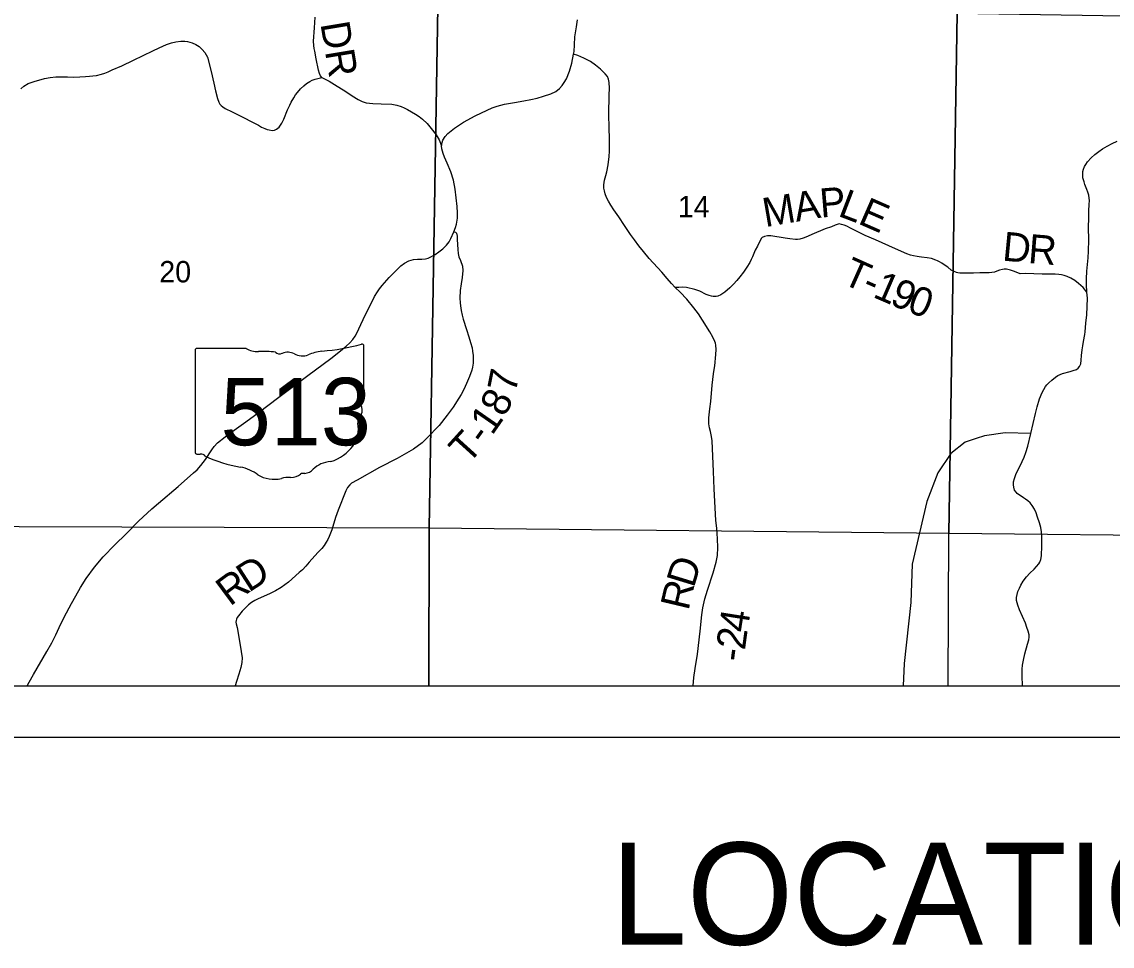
# Model space of a CAD drawing. Extents: x 0 to 34, y 0 to 22.
# Drawn here: x 3.275 to 5.408, y 13.591 to 15.399 of the extents above; entities that cross this region are included whole.
import ezdxf

# ---------------------------------------------------------------- set-up
doc = ezdxf.new("R2010")
doc.units = 0
for name, color, linetype in [('GM_X_Corporation', 7, 'Continuous'), ('GM_X_County_Road', 7, 'Continuous'), ('GM_X_County_Road_Text', 7, 'Continuous'), ('GM_X_Section_Text', 7, 'Continuous'), ('GM_X_State_Location', 7, 'Continuous'), ('GM_X_State_Route', 7, 'Continuous'), ('GM_X_State_Shield', 7, 'Continuous'), ('GM_X_Township_Road', 7, 'Continuous'), ('GM_X_Township_Road_Text', 7, 'Continuous'), ('GM_X_Township_Text', 7, 'Continuous'), ('SH_Data', 7, 'Continuous'), ('SH_Text', 7, 'Continuous')]:
    doc.layers.add(name, color=color, linetype=linetype)

msp = doc.modelspace()

# ---------------------------------------------------------------- linework, layer by layer
at = {"layer": 'GM_X_Corporation'}
for points in [[(3.0813, 15.4398), (4.0887, 15.4288), (4.0718, 14.4088), (3.0687, 14.4122)], [(4.0887, 15.4288), (5.1041, 15.416), (5.088, 14.3982), (4.0718, 14.4088)], [(5.1041, 15.416), (6.1226, 15.3998), (6.117, 14.3875), (5.088, 14.3982)], [(3.065, 14.1), (4.0712, 14.1), (4.0718, 14.4088), (3.0687, 14.4122)], [(4.0712, 14.1), (5.0867, 14.1), (5.088, 14.3982), (4.0718, 14.4088)]]:
    msp.add_lwpolyline(points, close=True, dxfattribs=at)
at = {"layer": 'GM_X_County_Road'}
msp.add_lwpolyline([(4.5879, 14.1), (4.5895, 14.1163), (4.5918, 14.1341), (4.5964, 14.1619), (4.6017, 14.2072), (4.6049, 14.2392), (4.6069, 14.253), (4.6106, 14.2702), (4.6158, 14.2874), (4.6272, 14.321), (4.6329, 14.3423), (4.6353, 14.355), (4.6359, 14.3706), (4.6355, 14.3878), (4.6343, 14.4089), (4.6325, 14.4237), (4.6288, 14.4857), (4.628, 14.5193), (4.625, 14.5798), (4.6238, 14.5883), (4.6217, 14.5975), (4.6198, 14.6053), (4.6187, 14.6128), (4.6185, 14.6179), (4.6188, 14.6247), (4.6206, 14.6419), (4.6222, 14.6563), (4.6254, 14.6883), (4.628, 14.7106), (4.6286, 14.7153), (4.6303, 14.7265), (4.6325, 14.7485), (4.633, 14.7585), (4.6323, 14.7666), (4.6313, 14.7706), (4.6302, 14.7738), (4.6262, 14.7824), (4.6204, 14.7928), (4.6063, 14.8155), (4.5982, 14.8278), (4.5892, 14.8398), (4.5758, 14.857), (4.5625, 14.8707), (4.5529, 14.8797), (4.5455, 14.8873), (4.5368, 14.8969), (4.5265, 14.9092), (4.5021, 14.936), (4.4906, 14.9497), (4.4819, 14.961), (4.473, 14.9729), (4.4653, 14.9833), (4.4538, 15.0006), (4.4424, 15.0181), (4.433, 15.0317), (4.4268, 15.0404), (4.4223, 15.0481), (4.4183, 15.0557), (4.4155, 15.0628), (4.4144, 15.0685), (4.4134, 15.0739), (4.4131, 15.0806), (4.4147, 15.0898), (4.417, 15.0986), (4.4192, 15.1061), (4.4219, 15.1192), (4.4237, 15.1359), (4.4242, 15.1465), (4.4242, 15.1561), (4.424, 15.1709), (4.4236, 15.1911), (4.4229, 15.2184), (4.4238, 15.256), (4.4244, 15.2692), (4.4238, 15.2808), (4.4226, 15.2874), (4.4201, 15.2925), (4.416, 15.2975), (4.4065, 15.3066), (4.3972, 15.3144), (4.3872, 15.3216), (4.3742, 15.3284), (4.3625, 15.3336), (4.3541, 15.3362)], dxfattribs=at)
at = {"layer": 'GM_X_State_Route'}
msp.add_lwpolyline([(3.2854, 14.1), (3.2894, 14.1076), (3.2977, 14.1227), (3.3236, 14.1677), (3.3333, 14.1841), (3.3416, 14.2003), (3.3479, 14.2141), (3.358, 14.2347), (3.3719, 14.2615), (3.3805, 14.2765), (3.3896, 14.2924), (3.4009, 14.3099), (3.4173, 14.3327), (3.4342, 14.3524), (3.4568, 14.3758), (3.4787, 14.3976), (3.5039, 14.4233), (3.5199, 14.4379), (3.5291, 14.4462), (3.5422, 14.4577), (3.5807, 14.4901), (3.6109, 14.5168), (3.6176, 14.5231), (3.6251, 14.5312), (3.6339, 14.5428), (3.6464, 14.5622), (3.6513, 14.5687), (3.6576, 14.5759), (3.6726, 14.5872), (3.69, 14.6002), (3.713, 14.617), (3.7369, 14.6345), (3.7774, 14.6648), (3.834, 14.7071), (3.8792, 14.7406), (3.8984, 14.7555), (3.909, 14.7645), (3.9165, 14.7713), (3.9221, 14.778), (3.9266, 14.7844), (3.9298, 14.7899), (3.9343, 14.7985), (3.9467, 14.8252), (3.9561, 14.8446), (3.9649, 14.8616), (3.9706, 14.871), (3.9746, 14.8769), (3.9798, 14.8836), (3.9936, 14.8994), (4.0074, 14.9135), (4.0164, 14.9218), (4.0234, 14.9271), (4.0318, 14.9317), (4.0365, 14.9332), (4.0408, 14.934), (4.0489, 14.9347), (4.0575, 14.9347), (4.0641, 14.9356), (4.0693, 14.937), (4.0738, 14.9389), (4.0832, 14.9441), (4.0906, 14.9491), (4.0981, 14.9551), (4.1055, 14.9624), (4.1082, 14.9657), (4.1104, 14.969), (4.114, 14.9752), (4.1199, 14.9883), (4.1229, 14.9967), (4.1248, 15.0034), (4.127, 15.0154), (4.1271, 15.0257), (4.1263, 15.0383), (4.1244, 15.0552), (4.1225, 15.072), (4.1195, 15.0898), (4.1138, 15.1061), (4.1065, 15.1225), (4.1017, 15.1345), (4.0988, 15.1417), (4.0966, 15.1508), (4.096, 15.1567), (4.0969, 15.1629), (4.0985, 15.1677), (4.1026, 15.1747), (4.1081, 15.181), (4.121, 15.191), (4.1387, 15.2028), (4.1614, 15.2156), (4.1851, 15.2267), (4.1948, 15.2308), (4.2048, 15.234), (4.2187, 15.238), (4.2384, 15.2417), (4.2568, 15.2444), (4.2702, 15.2471), (4.283, 15.2498), (4.2954, 15.2537), (4.3097, 15.2582), (4.3193, 15.2632), (4.3266, 15.2687), (4.3318, 15.2744), (4.3359, 15.2805), (4.3399, 15.2878), (4.3461, 15.3028), (4.3508, 15.3182), (4.3541, 15.3362), (4.3549, 15.3411), (4.3556, 15.3545), (4.3565, 15.3698), (4.3597, 15.3897), (4.3618, 15.4031)], dxfattribs=at)
at = {"layer": 'GM_X_State_Shield'}
for p, q in [((3.7139, 14.7604), (3.6173, 14.7604)), ((3.9437, 14.6606), (3.9437, 14.7653)), ((3.6141, 14.7569), (3.6141, 14.5568)), ((3.9436, 14.6607), (3.9437, 14.6606))]:
    msp.add_line(p, q, dxfattribs=at)
for centre, major_axis, start_param, end_param in [((3.6179, 14.7573), (0.00382, 0), 1.712693, 3.28349), ((3.7368, 14.7836), (0.037, 0), 4.042523, 4.731795), ((3.8263, 15.0332), (0.3495, 0), 4.814394, 5.042369), ((3.94, 14.7657), (0.00367, 0), 6.141152, 7.989035), ((3.7491, 14.648), (0.133, 0), 1.404758, 1.657858), ((3.7793, 14.7584), (0.0107, 0), 3.836095, 5.185415), ((3.795, 14.7352), (0.0222, 0), 0.950623, 2.079405), ((3.8237, 14.767), (0.0267, 0), 4.081561, 5.145723), ((3.8708, 14.6992), (0.0703, 0), 1.699011, 2.107814), ((3.9428, 14.6529), (0.00568, 0), 1.883978, 3.671073), ((3.9398, 14.6602), (0.00393, 0), 5.05454, 6.418171), ((3.9568, 14.6168), (0.0248, 0), 2.387724, 3.262537), ((3.9067, 14.6397), (0.0341, 0), 5.934695, 6.695948), ((3.8458, 14.6035), (0.0874, 0), 5.101752, 6.440018), ((3.6179, 14.5564), (0.00385, 0), 3.00124, 4.508301), ((3.6185, 14.5768), (0.0294, 0), 4.665946, 4.897461), ((3.6245, 14.5452), (0.0106, 0), 0.519207, 1.627899), ((3.7583, 14.725), (0.2524, 0), 4.195997, 4.488961), ((3.6831, 14.4669), (0.079, 0), 0.823519, 1.323587), ((3.822, 14.5374), (0.0282, 0), 4.937069, 5.64225), ((3.8827, 14.5006), (0.0479, 0), 1.647645, 2.488434), ((3.7685, 14.5443), (0.0501, 0), 4.026481, 4.996735), ((3.7974, 14.4751), (0.0412, 0), 1.495662, 1.94098), ((3.8011, 14.5293), (0.0267, 0), 4.691044, 5.507374), ((3.8252, 14.5099), (0.00752, 0), 1.147584, 2.315152)]:
    msp.add_ellipse(centre, major_axis=major_axis, ratio=0.8, start_param=start_param, end_param=end_param, dxfattribs=at)
at = {"layer": 'GM_X_Township_Road'}
for points in [[(3.8619, 15.2903), (3.8591, 15.2939), (3.857, 15.2982), (3.8549, 15.3045), (3.8503, 15.3271), (3.8478, 15.3416), (3.8467, 15.3469), (3.8457, 15.3532), (3.8454, 15.3615), (3.846, 15.3701), (3.8467, 15.3793), (3.8475, 15.3878), (3.8488, 15.4087)], [(3.2732, 15.2682), (3.279, 15.2737), (3.2871, 15.2787), (3.2989, 15.2828), (3.3192, 15.2886), (3.3305, 15.2902), (3.3414, 15.2914), (3.3539, 15.2916), (3.3642, 15.2915), (3.375, 15.291), (3.3884, 15.2917), (3.3997, 15.2924), (3.4072, 15.2931), (3.4137, 15.2937), (3.4212, 15.2946), (3.4309, 15.2968), (3.4375, 15.2989), (3.4438, 15.3015), (3.4518, 15.3051), (3.4702, 15.3134), (3.4934, 15.3243), (3.5309, 15.3424), (3.5438, 15.3487), (3.5579, 15.3549), (3.5673, 15.3581), (3.576, 15.36), (3.5857, 15.3613), (3.594, 15.3612), (3.5992, 15.3606), (3.608, 15.3585), (3.615, 15.3552), (3.6218, 15.3507), (3.6276, 15.345), (3.6326, 15.3391), (3.6379, 15.33), (3.6449, 15.3022), (3.6504, 15.2794), (3.6538, 15.2645), (3.6576, 15.249), (3.6603, 15.2421), (3.6622, 15.2385), (3.6649, 15.2353), (3.6677, 15.233), (3.6726, 15.23), (3.6862, 15.2234), (3.7059, 15.2137), (3.7271, 15.2023), (3.7375, 15.1968), (3.7436, 15.1934), (3.7503, 15.1904), (3.7547, 15.1888), (3.7588, 15.1877), (3.7643, 15.1869), (3.7689, 15.1876), (3.7731, 15.189), (3.7781, 15.1929), (3.7833, 15.2012), (3.7871, 15.2089), (3.7945, 15.2268), (3.7989, 15.2363), (3.8016, 15.2424), (3.8066, 15.2508), (3.8101, 15.2563), (3.8138, 15.2609), (3.8198, 15.268), (3.8262, 15.2738), (3.8319, 15.2783), (3.8383, 15.2823), (3.8429, 15.2849), (3.8488, 15.2872), (3.8619, 15.2903)], [(3.8619, 15.2903), (3.8762, 15.2832), (3.8867, 15.2769), (3.9086, 15.2632), (3.9213, 15.2545), (3.9327, 15.2473), (3.9407, 15.2437), (3.9486, 15.241), (3.9611, 15.2394), (3.9775, 15.2388), (3.9983, 15.2379), (4.0083, 15.2361), (4.0165, 15.2336), (4.0229, 15.2312), (4.0292, 15.2276), (4.0368, 15.2234), (4.0451, 15.2185), (4.052, 15.2142), (4.0585, 15.2088), (4.0675, 15.2001), (4.0752, 15.1909), (4.0854, 15.1779), (4.0911, 15.1684), (4.096, 15.1567)], [(5.2319, 14.1), (5.2313, 14.12), (5.2313, 14.133), (5.2324, 14.1404), (5.2338, 14.1507), (5.2367, 14.1629), (5.2416, 14.1816), (5.2444, 14.1903), (5.2451, 14.1954), (5.2448, 14.2003), (5.2429, 14.2071), (5.2407, 14.2144), (5.2378, 14.2226), (5.2265, 14.2488), (5.223, 14.2582), (5.2216, 14.2623), (5.2203, 14.267), (5.2206, 14.2728), (5.2216, 14.2792), (5.2232, 14.2848), (5.2263, 14.2915), (5.2288, 14.297), (5.2335, 14.3048), (5.24, 14.3134), (5.2464, 14.3205), (5.255, 14.3285), (5.2639, 14.3388), (5.2662, 14.342), (5.2681, 14.3472), (5.2693, 14.3546), (5.2699, 14.3743), (5.27, 14.3926), (5.2695, 14.4016), (5.2678, 14.4102), (5.2651, 14.419), (5.2612, 14.4303), (5.2585, 14.4387), (5.2557, 14.4461), (5.2513, 14.4528), (5.2469, 14.4581), (5.2428, 14.4621), (5.2379, 14.4657), (5.2338, 14.4682), (5.2297, 14.471), (5.2245, 14.4743), (5.2216, 14.4765), (5.2197, 14.4791), (5.2165, 14.4832), (5.215, 14.4887), (5.2144, 14.4935), (5.2147, 14.4991), (5.2162, 14.5056), (5.2189, 14.5134), (5.2315, 14.5388), (5.2353, 14.5475), (5.2389, 14.5569), (5.2427, 14.5694), (5.2482, 14.5938), (5.2575, 14.6327), (5.2609, 14.6459), (5.2651, 14.6614), (5.2704, 14.6739), (5.2737, 14.6802), (5.277, 14.6856), (5.2796, 14.689), (5.2837, 14.6931), (5.2897, 14.6985), (5.2965, 14.7044), (5.3011, 14.7075), (5.3055, 14.7095), (5.3104, 14.7111), (5.3254, 14.7152), (5.331, 14.7171), (5.3375, 14.7193), (5.3412, 14.7218), (5.3438, 14.725), (5.346, 14.7304), (5.3471, 14.7372), (5.3476, 14.7462), (5.349, 14.7575), (5.35, 14.7656), (5.3514, 14.774), (5.3537, 14.7875), (5.3546, 14.7931), (5.356, 14.81), (5.3579, 14.8261), (5.3589, 14.8586), (5.3582, 14.8705), (5.3574, 14.8855), (5.3572, 14.8963), (5.3578, 14.9118), (5.3604, 14.9376), (5.3612, 14.9508), (5.3617, 14.973), (5.3611, 14.9971), (5.3615, 15.0161), (5.3618, 15.0296), (5.3624, 15.042), (5.3629, 15.0497), (5.3625, 15.0546), (5.3619, 15.0599), (5.3601, 15.066), (5.3581, 15.0713), (5.3542, 15.0811), (5.3525, 15.086), (5.3502, 15.094), (5.3498, 15.0985), (5.3499, 15.1032), (5.3503, 15.1067), (5.3512, 15.111), (5.3534, 15.1163), (5.3559, 15.1204), (5.3593, 15.1254), (5.3661, 15.133), (5.3735, 15.1396), (5.3815, 15.1459), (5.3885, 15.1507), (5.3978, 15.1562), (5.4075, 15.1611), (5.4173, 15.1656)], [(5.3582, 14.8705), (5.3507, 14.8793), (5.3419, 14.8873), (5.3344, 14.8931), (5.3266, 14.8979), (5.3194, 14.9012), (5.3133, 14.9033), (5.3081, 14.9043), (5.303, 14.905), (5.2961, 14.9055), (5.2835, 14.9054), (5.2705, 14.9056), (5.2381, 14.9068), (5.2277, 14.9065), (5.2167, 14.9105), (5.2089, 14.9135), (5.2009, 14.9151), (5.1965, 14.9153), (5.1927, 14.9149), (5.1871, 14.9136), (5.182, 14.9115), (5.1775, 14.9098), (5.1719, 14.9087), (5.1668, 14.9084), (5.1579, 14.9081), (5.1486, 14.9082), (5.1362, 14.9076), (5.1269, 14.9074), (5.1181, 14.9074), (5.1092, 14.9075), (5.1057, 14.908), (5.1029, 14.9087), (5.097, 14.9112), (5.0924, 14.9137), (5.0858, 14.9191), (5.0791, 14.924), (5.0742, 14.9271), (5.0695, 14.9297), (5.066, 14.9316), (5.0625, 14.9331), (5.054, 14.936), (5.0455, 14.9377), (5.0343, 14.9389), (5.0299, 14.9394), (5.0263, 14.9399), (5.0191, 14.9415), (5.0127, 14.9429), (5.0058, 14.9455), (4.9838, 14.9553), (4.9445, 14.9728), (4.9246, 14.9815), (4.8959, 14.9957), (4.8888, 14.9992), (4.8836, 15.0015), (4.878, 15.0031), (4.8735, 15.0038), (4.8693, 15.0027), (4.8655, 15.0012), (4.8582, 14.9985), (4.8463, 14.9941), (4.8416, 14.9921), (4.8245, 14.985), (4.8086, 14.9781), (4.8034, 14.9763), (4.7965, 14.9744), (4.7919, 14.9737), (4.788, 14.9736), (4.7773, 14.9747), (4.7678, 14.9758), (4.7399, 14.9805), (4.7331, 14.9805), (4.7274, 14.9795), (4.7231, 14.9776), (4.7208, 14.9757), (4.7135, 14.9604), (4.7092, 14.9523), (4.7063, 14.9463), (4.7037, 14.9398), (4.7012, 14.9344), (4.6985, 14.9286), (4.693, 14.9194), (4.6861, 14.9098), (4.6793, 14.9007), (4.6732, 14.893), (4.6668, 14.886), (4.6594, 14.8786), (4.6496, 14.8706), (4.6419, 14.8655), (4.6364, 14.8627), (4.6331, 14.862), (4.6304, 14.8616), (4.6268, 14.8618), (4.6235, 14.8624), (4.6195, 14.8636), (4.6136, 14.8661), (4.6008, 14.8721), (4.5913, 14.8755), (4.5748, 14.8792), (4.5666, 14.8803), (4.5597, 14.8794), (4.5529, 14.8797)], [(4.1199, 14.9883), (4.1228, 14.9875), (4.1251, 14.9856), (4.1262, 14.9797), (4.1266, 14.9734), (4.1275, 14.9537), (4.1286, 14.9459), (4.1298, 14.9397), (4.1328, 14.9321), (4.1365, 14.921), (4.1375, 14.9128), (4.1359, 14.8989), (4.1339, 14.8869), (4.1321, 14.8736), (4.1315, 14.8588), (4.1321, 14.8497), (4.1328, 14.8434), (4.1344, 14.8343), (4.1361, 14.8257), (4.1383, 14.8178), (4.1449, 14.7974), (4.1492, 14.7831), (4.1524, 14.7718), (4.1555, 14.7616), (4.1565, 14.755), (4.1578, 14.7463), (4.1579, 14.7382), (4.1577, 14.7312), (4.1564, 14.7236), (4.155, 14.7176), (4.1505, 14.7052), (4.1444, 14.6915), (4.1391, 14.6797), (4.1341, 14.6705), (4.1294, 14.6627), (4.1184, 14.6452), (4.1071, 14.6296), (4.0909, 14.6097), (4.0672, 14.5847), (4.058, 14.5757), (4.0408, 14.5634), (4.0272, 14.5552), (4.0089, 14.5448), (3.9744, 14.5272), (3.9305, 14.5024), (3.9199, 14.4965), (3.9164, 14.4937), (3.9117, 14.4884), (3.9084, 14.4815), (3.8933, 14.4438), (3.8908, 14.4367), (3.8886, 14.4297), (3.8809, 14.4055), (3.8759, 14.3927), (3.8734, 14.3864), (3.8702, 14.3813), (3.8659, 14.3746), (3.8619, 14.3692), (3.854, 14.361), (3.8369, 14.342), (3.8305, 14.3343), (3.8239, 14.3275), (3.8176, 14.322), (3.7966, 14.3032), (3.7894, 14.2977), (3.7822, 14.2927), (3.7712, 14.2864), (3.7592, 14.2801), (3.737, 14.2703), (3.7304, 14.267), (3.724, 14.2633), (3.7185, 14.2588), (3.7141, 14.2546), (3.706, 14.246), (3.6989, 14.2373), (3.6963, 14.2338), (3.6946, 14.2308), (3.6938, 14.2278), (3.6937, 14.2248), (3.694, 14.2215), (3.6958, 14.2144), (3.7017, 14.1798), (3.7056, 14.1549), (3.7054, 14.146), (3.7029, 14.1358), (3.699, 14.1231), (3.6945, 14.1087), (3.6921, 14.1)], [(5.2482, 14.5938), (5.1984, 14.5955), (5.1577, 14.5892), (5.1417, 14.5839)], [(5.1417, 14.5839), (5.1357, 14.5819), (5.1201, 14.5767), (5.0919, 14.5547), (5.0668, 14.5171), (5.0448, 14.4607), (5.0166, 14.3385), (5.0135, 14.2633), (5.0009, 14.1442), (4.9984, 14.1)]]:
    msp.add_lwpolyline(points, dxfattribs=at)
at = {"layer": 'GM_X_Township_Text'}
msp.add_lwpolyline([(2.6249, 19.1744), (2.6223, 19.0497), (2.622, 19.0358), (2.6202, 18.9481), (2.604, 17.9706), (2.6039, 17.9669), (2.5791, 16.4754), (2.4938, 16.4762), (2.1, 16.4804), (2.1, 14.1), (7.1227, 14.1)], dxfattribs=at)
at = {"layer": 'SH_Data'}
for p, q in [((2.1, 14.1), (8.9, 14.1)), ((2, 14), (9, 14))]:
    msp.add_line(p, q, dxfattribs=at)

# ---------------------------------------------------------------- texts
at = {"layer": 'GM_X_County_Road_Text'}
for s, rotation, p in [('D', 72.9222, (4.589, 14.2903)), ('R', 76.6321, (4.5785, 14.2459)), ('4', 81.0814, (4.6937, 14.2028)), ('2', 82.3382, (4.6891, 14.1688)), ('-', 82.3931, (4.6861, 14.1458))]:
    msp.add_text(s, height=0.0568, rotation=rotation, dxfattribs=at).set_placement(p)
at = {"layer": 'GM_X_Section_Text'}
for s, p in [('14', (4.5579, 15.0169)), ('20', (3.5437, 14.8895))]:
    msp.add_text(s, height=0.04186, rotation=0, dxfattribs=at).set_placement(p)
at = {"layer": 'GM_X_State_Location'}
for s in ['s', 'r']:
    msp.add_text(s, height=0.000189, dxfattribs=at).set_placement((3.7752, 14.6435))
msp.add_text('513', height=0.000189, rotation=0, dxfattribs=at).set_placement((3.7083, 14.6298))
at = {"layer": 'GM_X_State_Shield'}
msp.add_text('513', height=0.13184, dxfattribs=at).set_placement((3.6636, 14.5709))
at = {"layer": 'GM_X_Township_Road_Text'}
for s, height, rotation, p in [('DR', 0.05682, 279.4626, (3.8587, 15.3957)), ('M', 0.0568, 9.7678, (4.7288, 14.9975)), ('A', 0.0568, 9.7073, (4.7896, 15.0079)), ('P', 0.0568, 4.7522, (4.8376, 15.0162)), ('L', 0.0568, 339.0422, (4.8691, 15.0203)), ('E', 0.0568, 336.3878, (4.9082, 15.0054)), ('D', 0.0568, 354.575, (5.1913, 14.9324)), ('R', 0.0568, 355.4077, (5.2419, 14.9276)), ('T', 0.0568, 335.9657, (4.8765, 14.8886)), ('-', 0.0568, 336.1185, (4.9154, 14.8712)), ('1', 0.0568, 336.6202, (4.9373, 14.8616)), ('9', 0.0568, 337.4374, (4.9702, 14.8473)), ('0', 0.0568, 338.6826, (5.0038, 14.8334)), ('7', 0.0568, 78.6999, (4.2406, 14.6717)), ('8', 0.0568, 62.6028, (4.2187, 14.6242)), ('1', 0.0568, 55.2072, (4.1946, 14.5886)), ('T', 0.0568, 47.7799, (4.1475, 14.5319)), ('-', 0.0568, 54.3877, (4.1805, 14.5689)), ('D', 0.0568, 32.8302, (3.7186, 14.2819)), ('R', 0.0568, 36.5381, (3.6819, 14.2547))]:
    msp.add_text(s, height=height, rotation=rotation, dxfattribs=at).set_placement(p)
at = {"layer": 'SH_Text'}
msp.add_text('LOCATION MAP', height=0.2, dxfattribs=at).set_placement((4.4269, 13.5937))

doc.saveas('drawing.dxf')
